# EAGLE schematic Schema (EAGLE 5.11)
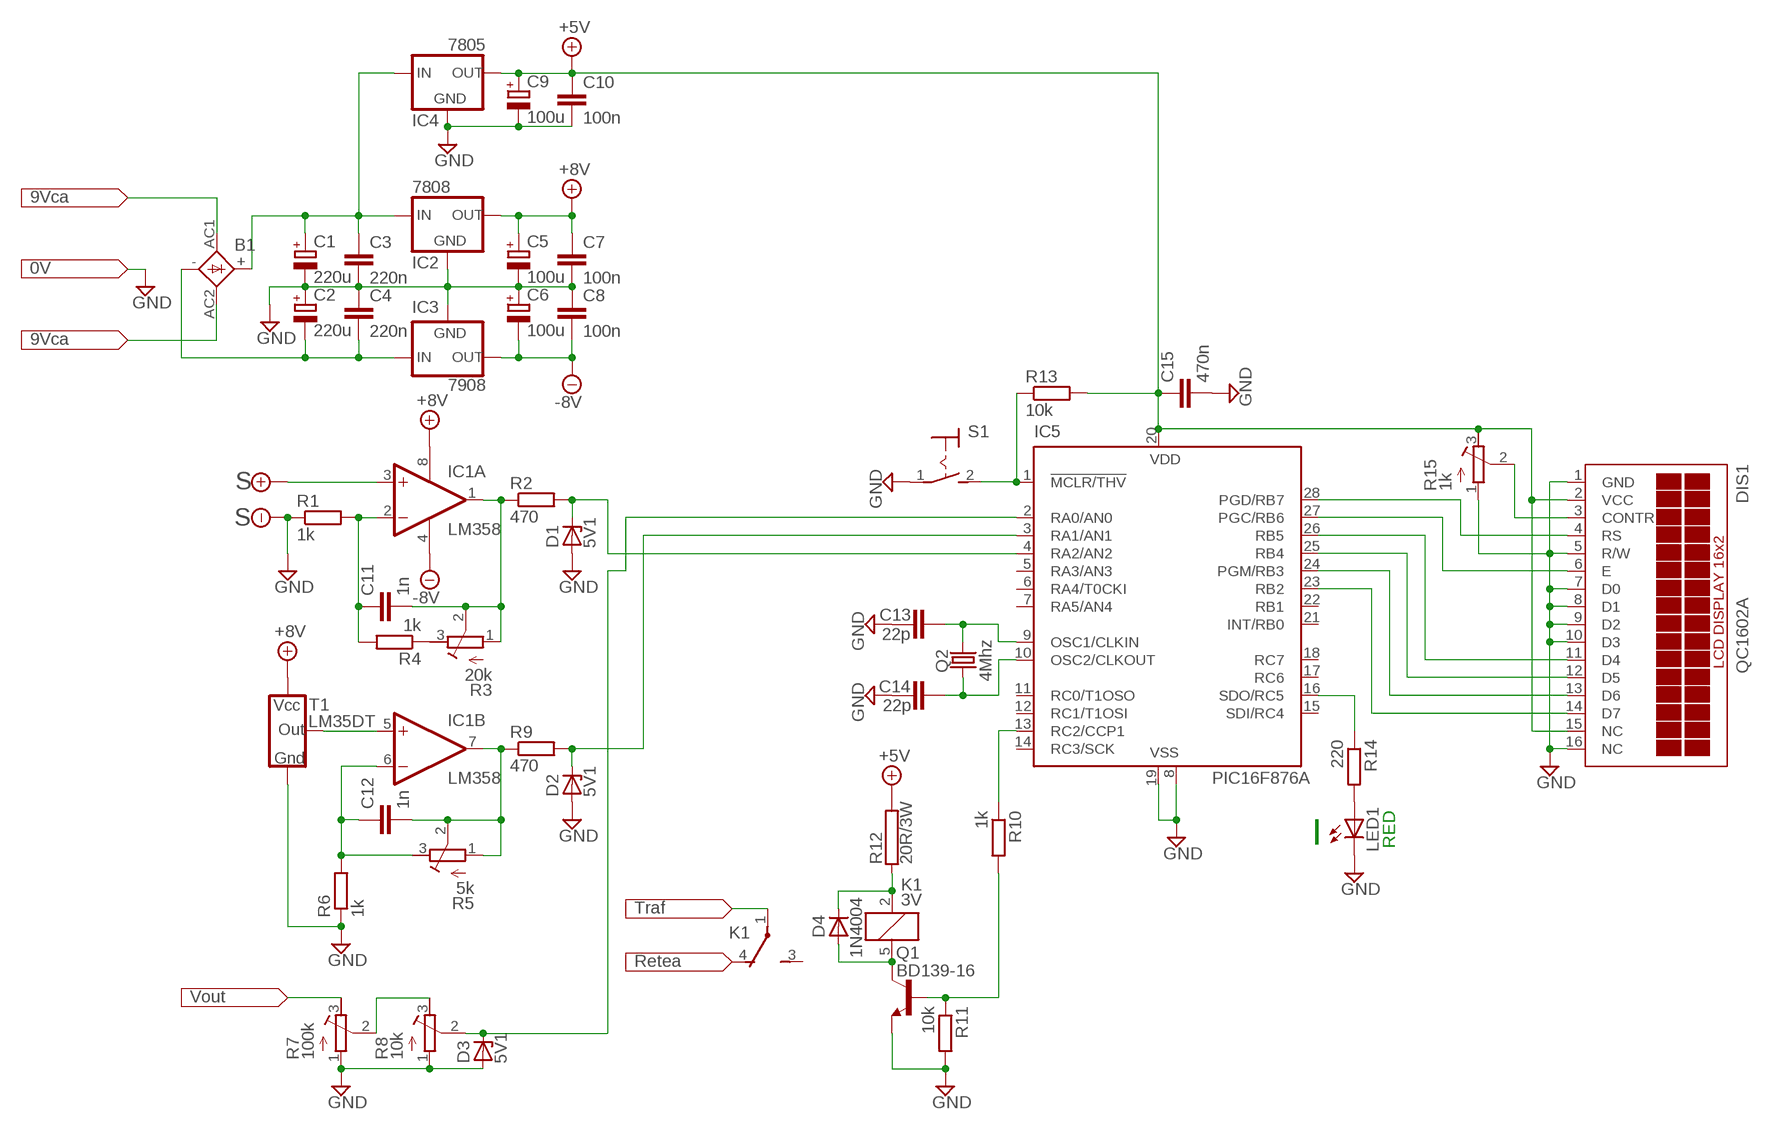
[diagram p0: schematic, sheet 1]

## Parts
B1  2KBB  [2KBB]
C1  220u  CPOL-EUE5-5  [E5-5]
C2  220u  CPOL-EUE5-5  [E5-5]
C3  220n  C-EU050-024X044  [C050-024X044]
C4  220n  C-EU050-024X044  [C050-024X044]
C5  100u  CPOL-EUE5-5  [E5-5]
C6  100u  CPOL-EUE5-5  [E5-5]
C7  100n  C-EU050-024X044  [C050-024X044]
C8  100n  C-EU050-024X044  [C050-024X044]
C9  100u  CPOL-EUE5-5  [E5-5]
C10  100n  C-EU050-024X044  [C050-024X044]
C11  1n  C-EU050-024X044  [C050-024X044]
C12  1n  C-EU050-024X044  [C050-024X044]
C13  22p  C-EU050-024X044  [C050-024X044]
C14  22p  C-EU050-024X044  [C050-024X044]
C15  470n  C-EU050-024X044  [C050-024X044]
D1  5V1  1N4728  [DO41Z10]
D2  5V1  1N4728  [DO41Z10]
D3  5V1  1N4728  [DO41Z10]
D4  1N4004  [DO41-10]
DIS1  QC1602A  TUXGR_16X2_R2  [TUXGR_16X2_R2]
IC1  LM358  AD8682R  [SO08]
IC2  7808  78LXX  [78LXX]
IC3  7908  79LXX  [79LXX]
IC4  7805  78LXX  [78LXX]
IC5  PIC16F876A  PIC16876P  [DIL28-3]
K1  3V  AZ8-FORM-C  [AZ8]
LED1  LED5MM  [LED5MM]
Q1  BD139-16  BD139  [TO126]
Q2  4Mhz  CRYSTALHC49S  [HC49/S]
R1  1k  R-EU_0207/10  [0207/10]
R2  470  R-EU_0207/10  [0207/10]
R3  20k  R-TRIMM64W  [RTRIM64W]
R4  1k  R-EU_0207/10  [0207/10]
R5  5k  R-TRIMM64W  [RTRIM64W]
R6  1k  R-EU_0207/10  [0207/10]
R7  100k  R-TRIMM64W  [RTRIM64W]
R8  10k  R-TRIMM64W  [RTRIM64W]
R9  470  R-EU_0207/10  [0207/10]
R10  1k  R-EU_0207/10  [0207/10]
R11  10k  R-EU_0207/10  [0207/10]
R12  20R/3W  RCA4055  [CA4055]
R13  10k  R-EU_0207/10  [0207/10]
R14  220  R-EU_0207/10  [0207/10]
R15  1k  R-TRIMM64W  [RTRIM64W]
S1  MS243  [MS243]
T1  LM35DT  LM353008  [LM35]

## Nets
+8V: C5.+ C7.1 C9.+ C10.1 C15.1 DIS1.2(VCC) DIS1.15(NC) IC1.3(A:+IN) IC1.8(P:V+) IC2.OUT IC4.OUT IC5.20(VDD) R12.2 R13.2 R15.3(A) T1.P$1 ; supply symbol labelled +5V, S
-8V: C6.- C8.2 IC1.4(P:V-) IC3.OUT
GND: C1.- C2.+ C3.2 C4.1 C5.- C6.+ C7.2 C8.1 C9.- C10.2 C13.1 C14.1 C15.2 D1.A D2.A D3.A DIS1.1(GND) DIS1.5(R/W) DIS1.7(D0) DIS1.8(D1) DIS1.9(D2) DIS1.10(D3) DIS1.16(NC) IC2.GND IC3.GND IC4.GND IC5.8(VSS) IC5.19(VSS) LED1.K(C) Q1.1(E) R1.1 R6.1 R7.1(E) R8.1(E) R11.2 R15.1(E) S1.1(P) T1.P$2 ; supply symbol labelled S
N$1: B1.AC1
N$2: B1.AC2
N$3: B1.- C2.- C4.2 IC3.IN
N$4: B1.+ C1.+ C3.1 IC2.IN IC4.IN
N$5: C11.1 IC1.2(A:-IN) R1.2 R4.2
N$6: C12.2 IC1.7(B:OUT) R5.1(E) R5.2(S) R9.1
N$7: C12.1 IC1.6(B:-IN) R5.3(A) R6.2
N$8: R3.3(A) R4.1
N$9: C11.2 IC1.1(A:OUT) R2.1 R3.1(E) R3.2(S)
N$10: IC5.1(!MCLR/THV) R13.1 S1.2(S)
N$11: IC1.5(B:+IN) T1.P$3
N$12: LED1.A R14.2
N$13: IC5.16(SDO/RC5) R14.1
N$14: R7.2(S) R8.3(A)
N$15: R7.3(A)
N$16: IC5.13(RC2/CCP1) R10.1
N$17: D1.C IC5.4(RA2/AN2) R2.2
N$18: D2.C IC5.3(RA1/AN1) R9.2
N$19: D3.C IC5.2(RA0/AN0) R8.2(S)
N$20: DIS1.14(D7) IC5.23(RB2)
N$21: C14.2 IC5.10(OSC2/CLKOUT) Q2.1
N$22: C13.2 IC5.9(OSC1/CLKIN) Q2.2
N$23: Q1.3(B) R10.2 R11.1
N$24: D4.C K1.2 R12.1
N$25: D4.A K1.5 Q1.2(C)
N$26: K1.1(-1:P)
N$27: DIS1.13(D6) IC5.24(PGM/RB3)
N$28: DIS1.12(D5) IC5.25(RB4)
N$29: DIS1.11(D4) IC5.26(RB5)
N$30: DIS1.6(E) IC5.27(PGC/RB6)
N$31: DIS1.4(RS) IC5.28(PGD/RB7)
N$35: DIS1.3(CONTR) R15.2(S)
Unconnected: IC5.5(RA3/AN3) IC5.6(RA4/T0CKI) IC5.7(RA5/AN4) IC5.11(RC0/T1OSO) IC5.12(RC1/T1OSI) IC5.14(RC3/SCK) IC5.15(SDI/RC4) IC5.17(RC6) IC5.18(RC7) IC5.21(INT/RB0) IC5.22(RB1) K1.3(-1:S) K1.4(-1:O)

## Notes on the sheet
- I | RED

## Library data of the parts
B1 = rectifier:2KBB: RECTIFIER grid 3 x 5 mm
C1 C2 C5 C6 C9 = resistor:CPOL-EU: POLARIZED CAPACITOR, European symbol
C3 C4 C7 C8 C10-C15 = resistor:C-EU: CAPACITOR, European symbol
D1-D3 = diode:1N4728: Z DIODE
D4 = diode:1N4004: DIODE
DIS1 = display-lcd:TUXGR_16X2_R2: Tuxgraphics LCD display 16x2 characters reflective, without background light Source: tuxgr_12x2_r2.pdf; OC_FARNELL: unknown; OC_NEWARK: unknown
IC1 = linear:AD8682: Dual Low Power, High Speed JFET Operational Amplifiers Source: http://www.analog.com/UploadedFiles/Data_Sheets/AD8682_8684.pdf
IC2 IC4 = v-reg:78LXX: VOLTAGE REGULATOR
IC3 = v-reg:79LXX: VOLTAGE REGULATOR
IC5 = microchip:PIC16*876: MICROCONTROLLER flash type; OC_FARNELL: unknown; OC_NEWARK: unknown
K1 = relay:AZ8-FORM-C: MINIATURE PC BOARD RELAY Form C Source: www.azettler.com .. AZ8-1ch-12DSE.PDF; OC_FARNELL: unknown; OC_NEWARK: unknown
LED1 = led:LED: LED
Q1 = transistor-npn:BD139*: NPN Transistor
Q2 = crystal:CRYSTAL: CRYSTAL; OC_FARNELL: 1667008; OC_NEWARK: unknown
R1 R2 R4 R6 R9-R11 R13 R14 = resistor:R-EU_: RESISTOR, European symbol
R3 R5 R7 R8 R15 = resistor:R-TRIMM: Trimm resistor
R12 = resistor-power:R: Power Resitor; OC_FARNELL: unknown; OC_NEWARK: unknown
S1 = switch:MS243: TOGGLE SWITCH
T1 = LM35#3:LM35: Precision Centigrade Temperature Sensors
